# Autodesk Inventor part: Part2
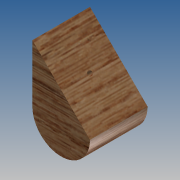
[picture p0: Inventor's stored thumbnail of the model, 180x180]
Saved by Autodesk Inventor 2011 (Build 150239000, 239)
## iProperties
Created: 2011-01
Part Number: Part2
Document SubType Name: Modeling
Designer: Microsoft
Density: 1 g/cm^3
Author: Microsoft
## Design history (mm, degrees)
sketch "Sketch1"
  geometry: L1 (9.525, 0)-(9.525, 19.05); L2 (-9.525, 19.05)-(-9.525, 0); L3 (-9.525, 19.05)-(9.525, 0); A1 r 9.525 centre (0, 0) between (-9.525, 0) and (9.525, 0); A2 r 9.525 centre (0, 19.05) between (9.525, 19.05) and (-9.525, 19.05); 1 further point
  constraints: 6 end point, 4 point on circle, 3 tangent, 2 centre point, 1 coincident, 1 vertical alignment
  dimensions: "d3" = 9.525 radius of A2; "d4" = 9.525 radius of A1; "d5" = 19.05 distance of L1.start L1.end; "d6" = 19.05 distance of point (0, 0) A2.centre
extrude "Extrusion1" new body sketch "Sketch1" distance "d7" = 19.05; taper "d8" = 0 deg
sketch "Sketch2"
  geometry: L1 (13.47, 0)-(13.47, 19.05) reference; C1 r 0.794 at (13.47, 9.525); 1 further point
  constraints: 1 centre point, 1 midpoint
  dimensions: "d9" = 1.5875 diameter of C1
extrude "Extrusion2" cut sketch "Sketch2" distance "d10" = 6.35; taper "d11" = 0 deg
sketch "Sketch3"
  geometry: C1 r 0.794 at (0, 0) reference; C2 r 1.587 at (0, 0); 1 further point
  constraints: 1 centre point, 1 coincident
  dimensions: "d12" = 3.175 diameter of C2
extrude "Extrusion3" cut sketch "Sketch3" distance "d13" = 0.79375; taper "d14" = 0 deg
body "Solid1"
